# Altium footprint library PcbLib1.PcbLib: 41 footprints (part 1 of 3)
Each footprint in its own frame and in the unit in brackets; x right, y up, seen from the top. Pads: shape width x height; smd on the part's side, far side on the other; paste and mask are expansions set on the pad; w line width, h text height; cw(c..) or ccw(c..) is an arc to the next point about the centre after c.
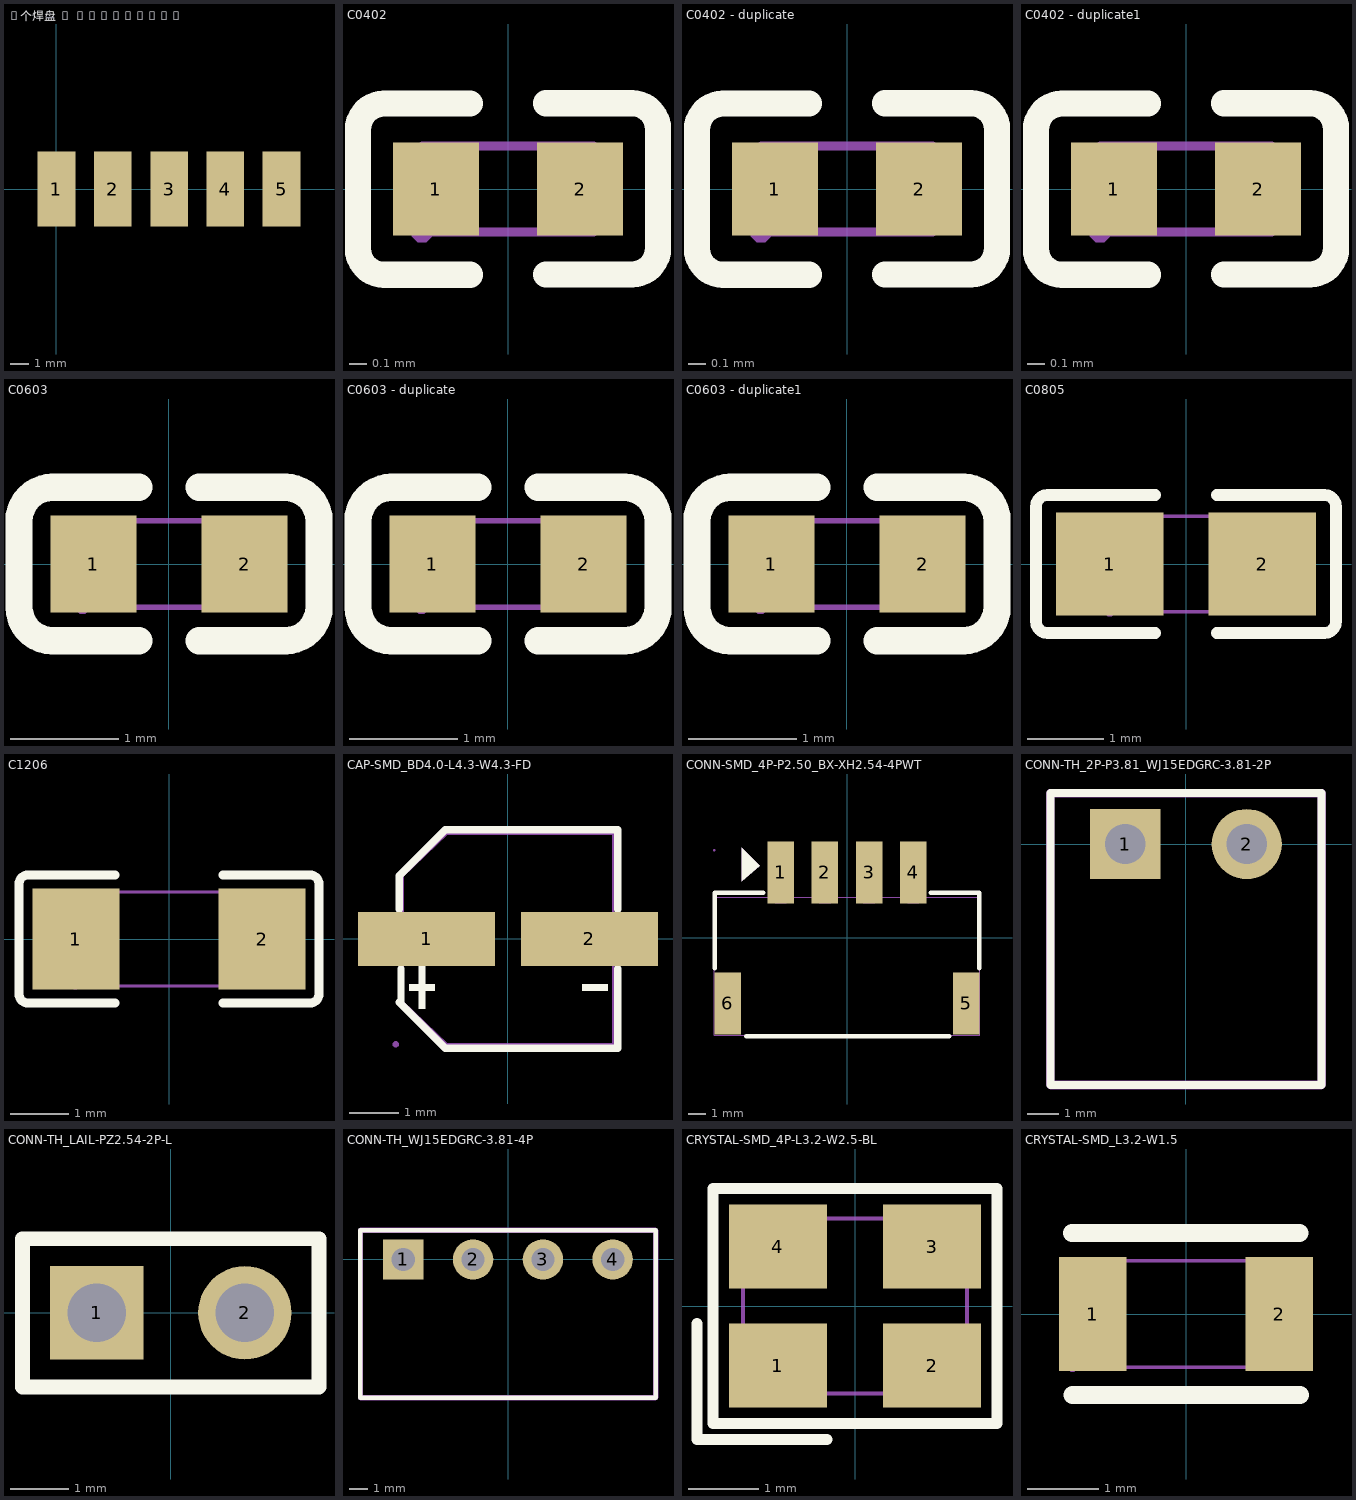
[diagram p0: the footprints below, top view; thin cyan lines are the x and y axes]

## 5个焊盘 - duplicate [mm]
pads (5):
  rect 2x4 smd: 1(0,0) 2(3,0) 3(6.001,0) 4(9,0) 5(12,0)

## C0402 [mm]
pads (2):
  rect 0.5x0.54 smd: 1(-0.42,0) 2(0.42,0)
Top Overlay:
  lines w0.152: -0.221,-0.5 -0.721,-0.5 cw(c-0.721,-0.347) -0.874,-0.347 -0.874,0.345 cw(c-0.721,0.345) -0.721,0.498 -0.221,0.498 ; 0.221,-0.498 0.721,-0.498 ccw(c0.721,-0.345) 0.874,-0.345 0.874,0.347 ccw(c0.721,0.347) 0.721,0.5 0.221,0.5
Mechanical 6:
  lines w0.051: -0.5,-0.25 0.5,-0.25 0.5,0.25 -0.5,0.25 -0.5,-0.25
Mechanical 8:
  region: -0.44,-0.25 -0.44,-0.275 -0.475,-0.31 -0.525,-0.31 -0.56,-0.275 -0.56,-0.25 -0.56,-0.225 -0.525,-0.19 -0.475,-0.19 -0.44,-0.225 -0.44,-0.25
Mechanical 9:
  region: 0.5,-0.25 0.5,0.25 0.25,0.25 0.25,-0.25
  region: -0.5,-0.25 -0.5,0.25 -0.25,0.25 -0.25,-0.25

## C0402 - duplicate [mm]
pads (2):
  rect 0.5x0.54 smd: 1(-0.42,0) 2(0.42,0)
Top Overlay:
  lines w0.152: -0.221,-0.5 -0.721,-0.5 cw(c-0.721,-0.347) -0.874,-0.347 -0.874,0.345 cw(c-0.721,0.345) -0.721,0.498 -0.221,0.498 ; 0.221,-0.498 0.721,-0.498 ccw(c0.721,-0.345) 0.874,-0.345 0.874,0.347 ccw(c0.721,0.347) 0.721,0.5 0.221,0.5
Mechanical 6:
  lines w0.051: -0.5,-0.25 0.5,-0.25 0.5,0.25 -0.5,0.25 -0.5,-0.25
Mechanical 8:
  region: -0.44,-0.25 -0.44,-0.275 -0.475,-0.31 -0.525,-0.31 -0.56,-0.275 -0.56,-0.25 -0.56,-0.225 -0.525,-0.19 -0.475,-0.19 -0.44,-0.225 -0.44,-0.25
Mechanical 9:
  region: 0.5,-0.25 0.5,0.25 0.25,0.25 0.25,-0.25
  region: -0.5,-0.25 -0.5,0.25 -0.25,0.25 -0.25,-0.25

## C0402 - duplicate1 [mm]
pads (2):
  rect 0.5x0.54 smd: 1(-0.42,0) 2(0.42,0)
Top Overlay:
  lines w0.152: -0.221,-0.5 -0.721,-0.5 cw(c-0.721,-0.347) -0.874,-0.347 -0.874,0.345 cw(c-0.721,0.345) -0.721,0.498 -0.221,0.498 ; 0.221,-0.498 0.721,-0.498 ccw(c0.721,-0.345) 0.874,-0.345 0.874,0.347 ccw(c0.721,0.347) 0.721,0.5 0.221,0.5
Mechanical 6:
  lines w0.051: -0.5,-0.25 0.5,-0.25 0.5,0.25 -0.5,0.25 -0.5,-0.25
Mechanical 8:
  region: -0.44,-0.25 -0.44,-0.275 -0.475,-0.31 -0.525,-0.31 -0.56,-0.275 -0.56,-0.25 -0.56,-0.225 -0.525,-0.19 -0.475,-0.19 -0.44,-0.225 -0.44,-0.25
Mechanical 9:
  region: 0.5,-0.25 0.5,0.25 0.25,0.25 0.25,-0.25
  region: -0.5,-0.25 -0.5,0.25 -0.25,0.25 -0.25,-0.25

## C0603 [mm]
pads (2):
  rect 0.8x0.9 smd: 1(-0.7,0) 2(0.7,0)
Top Overlay:
  lines w0.254: -1.08,-0.71 -0.28,-0.71 ; -1.08,0.71 -0.28,0.71 ; -1.08,-0.71 cw(c-1.08,-0.4) -1.39,-0.4 -1.39,0.4 cw(c-1.08,0.4) -1.08,0.71 ; 0.28,-0.71 1.08,-0.71 ccw(c1.08,-0.4) 1.39,-0.4 1.39,0.4 ccw(c1.08,0.4) 1.08,0.71 0.28,0.71
Mechanical 6:
  lines w0.051: -0.8,-0.4 -0.8,0.4 0.8,0.4 0.8,-0.4 -0.8,-0.4
Mechanical 8:
  region: -0.74,-0.4 -0.74,-0.425 -0.775,-0.46 -0.825,-0.46 -0.86,-0.425 -0.86,-0.4 -0.86,-0.375 -0.825,-0.34 -0.775,-0.34 -0.74,-0.375 -0.74,-0.4
Mechanical 9:
  region: -0.8,-0.4 -0.8,0.4 -0.5,0.4 -0.5,-0.4
  region: 0.8,-0.4 0.8,0.4 0.5,0.4 0.5,-0.4

## C0603 - duplicate [mm]
pads (2):
  rect 0.8x0.9 smd: 1(-0.7,0) 2(0.7,0)
Top Overlay:
  lines w0.254: -1.08,-0.71 -0.28,-0.71 ; -1.08,0.71 -0.28,0.71 ; -1.08,-0.71 cw(c-1.08,-0.4) -1.39,-0.4 -1.39,0.4 cw(c-1.08,0.4) -1.08,0.71 ; 0.28,-0.71 1.08,-0.71 ccw(c1.08,-0.4) 1.39,-0.4 1.39,0.4 ccw(c1.08,0.4) 1.08,0.71 0.28,0.71
Mechanical 6:
  lines w0.051: -0.8,-0.4 0.8,-0.4 0.8,0.4 -0.8,0.4 -0.8,-0.4
Mechanical 8:
  region: -0.74,-0.4 -0.74,-0.425 -0.775,-0.46 -0.825,-0.46 -0.86,-0.425 -0.86,-0.4 -0.86,-0.375 -0.825,-0.34 -0.775,-0.34 -0.74,-0.375 -0.74,-0.4
Mechanical 9:
  region: 0.8,-0.4 0.8,0.4 0.5,0.4 0.5,-0.4
  region: -0.8,-0.4 -0.8,0.4 -0.5,0.4 -0.5,-0.4

## C0603 - duplicate1 [mm]
pads (2):
  rect 0.8x0.9 smd: 1(-0.7,0) 2(0.7,0)
Top Overlay:
  lines w0.254: -1.08,-0.71 -0.28,-0.71 ; -1.08,0.71 -0.28,0.71 ; -1.08,-0.71 cw(c-1.08,-0.4) -1.39,-0.4 -1.39,0.4 cw(c-1.08,0.4) -1.08,0.71 ; 0.28,-0.71 1.08,-0.71 ccw(c1.08,-0.4) 1.39,-0.4 1.39,0.4 ccw(c1.08,0.4) 1.08,0.71 0.28,0.71
Mechanical 6:
  lines w0.051: -0.8,-0.4 -0.8,0.4 0.8,0.4 0.8,-0.4 -0.8,-0.4
Mechanical 8:
  region: -0.74,-0.4 -0.74,-0.425 -0.775,-0.46 -0.825,-0.46 -0.86,-0.425 -0.86,-0.4 -0.86,-0.375 -0.825,-0.34 -0.775,-0.34 -0.74,-0.375 -0.74,-0.4
Mechanical 9:
  region: -0.8,-0.4 -0.8,0.4 -0.5,0.4 -0.5,-0.4
  region: 0.8,-0.4 0.8,0.4 0.5,0.4 0.5,-0.4

## C0805 [mm]
pads (2):
  rect 1.41x1.35 smd paste-100 mask+0.051: 1(-1,0) 2(1,0)
Top Overlay:
  lines w0.152: -0.401,-0.904 -1.811,-0.904 cw(c-1.811,-0.751) -1.964,-0.751 -1.964,0.751 cw(c-1.811,0.751) -1.811,0.904 -0.401,0.904 ; 0.401,-0.904 1.811,-0.904 ccw(c1.811,-0.751) 1.964,-0.751 1.964,0.751 ccw(c1.811,0.751) 1.811,0.904 0.401,0.904
Top Paste:
  region: -1.705,-0.64 -1.705,0.64 -1.655,0.69 -0.505,0.69 -0.455,0.64 -0.45,0.23 -0.9,0.23 -0.9,-0.22 -0.46,-0.22 -0.455,-0.64 -0.505,-0.69 -1.655,-0.69
  region: 1.705,0.64 1.705,-0.64 1.655,-0.69 0.505,-0.69 0.455,-0.64 0.45,-0.23 0.9,-0.23 0.9,0.22 0.46,0.22 0.455,0.64 0.505,0.69 1.655,0.69
Mechanical 6:
  lines w0.051: -1,-0.625 -1,0.625 1,0.625 1,-0.625 -1,-0.625
Mechanical 8:
  region: -0.94,-0.625 -0.94,-0.65 -0.975,-0.685 -1.025,-0.685 -1.06,-0.65 -1.06,-0.625 -1.06,-0.6 -1.025,-0.565 -0.975,-0.565 -0.94,-0.6 -0.94,-0.625
Mechanical 9:
  region: -1,-0.625 -1,0.625 -0.5,0.625 -0.5,-0.625
  region: 1,0.625 1,-0.625 0.5,-0.625 0.5,0.625

## C1206 [mm]
pads (2):
  rect 1.485x1.728 smd paste-100 mask+0.051: 1(-1.593,0) 2(1.593,0)
Top Overlay:
  lines w0.152: -0.926,-1.093 -2.411,-1.093 cw(c-2.411,-0.94) -2.564,-0.94 -2.564,0.94 cw(c-2.411,0.94) -2.411,1.093 -0.926,1.093 ; 0.926,-1.093 2.411,-1.093 ccw(c2.411,-0.94) 2.564,-0.94 2.564,0.94 ccw(c2.411,0.94) 2.411,1.093 0.926,1.093
Top Paste:
  region: -0.85,-0.764 -0.85,-0.394 -0.95,-0.294 -1.255,-0.294 -1.355,-0.194 -1.355,0.194 -1.255,0.294 -0.95,0.294 -0.85,0.394 -0.85,0.764 -0.95,0.864 -2.235,0.864 -2.335,0.764 -2.335,-0.764 -2.235,-0.864 -0.95,-0.864
  region: 0.85,-0.764 0.85,-0.394 0.95,-0.294 1.255,-0.294 1.355,-0.194 1.355,0.194 1.255,0.294 0.95,0.294 0.85,0.394 0.85,0.764 0.95,0.864 2.235,0.864 2.335,0.764 2.335,-0.764 2.235,-0.864 0.95,-0.864
Mechanical 6:
  lines w0.051: -1.6,-0.8 1.6,-0.8 1.6,0.8 -1.6,0.8 -1.6,-0.8
Mechanical 8:
  region: -1.54,-0.8 -1.54,-0.825 -1.575,-0.86 -1.625,-0.86 -1.66,-0.825 -1.66,-0.8 -1.66,-0.775 -1.625,-0.74 -1.575,-0.74 -1.54,-0.775 -1.54,-0.8
Mechanical 9:
  region: 1.6,-0.8 1.6,0.8 1.1,0.8 1.1,-0.8
  region: -1.6,-0.8 -1.6,0.8 -1.1,0.8 -1.1,-0.8

## CAP-SMD_BD4.0-L4.3-W4.3-FD [mm]
pads (2):
  rect 2.8x1.1 smd: 1(-1.661,0) 2(1.661,0)
Top Overlay:
  region: -1.818,-0.559 -1.818,-1.419 -1.689,-1.419 -1.689,-0.559
  region: -2.011,-0.925 -2.011,-1.054 -1.495,-1.054 -1.495,-0.925
  region: 2.031,-0.925 2.031,-1.054 1.515,-1.054 1.515,-0.925
  lines w0.152: -2.217,-1.29 -1.28,-2.226 2.236,-2.226 2.236,-0.607 ; -2.217,0.607 -2.217,1.29 -1.28,2.226 2.236,2.226 2.236,0.607 ; -2.183,-1.29 -2.183,-0.607
Mechanical 2:
  region: -1.818,0.43 -1.818,-0.43 -1.689,-0.43 -1.689,0.43
  region: -2.011,0.064 -2.011,-0.065 -1.495,-0.065 -1.495,0.064
  region: 2.031,0.064 2.031,-0.065 1.515,-0.065 1.515,0.064
Mechanical 6:
  lines w0.051: -2.15,-1.281 -2.15,1.281 -1.248,2.15 2.15,2.15 2.15,-2.15 -1.248,-2.15 -2.15,-1.281
Mechanical 8:
  region: -2.23,-2.15 -2.23,-2.175 -2.266,-2.21 -2.315,-2.21 -2.35,-2.175 -2.35,-2.15 -2.35,-2.125 -2.315,-2.09 -2.266,-2.09 -2.23,-2.125 -2.23,-2.15
Mechanical 9:
  region: -2.29,0.325 -2.29,-0.325 -0.49,-0.325 -0.49,0.325
  region: 2.31,0.325 2.31,-0.325 0.51,-0.325 0.51,0.325

## CONN-SMD_4P-P2.50_BX-XH2.54-4PWT [mm]
pads (6):
  rect 1.5x3.5 smd paste+0 mask+0.05: 1(-3.75,3.7) 2(-1.25,3.7) 3(1.25,3.7) 4(3.75,3.7) 5(6.73,-3.7) 6(-6.73,-3.7)
Top Overlay:
  region: -4.946,4.081 -5.962,5.097 -5.962,3.192
  lines w0.254: -7.486,-1.719 -7.486,2.557 -4.731,2.557 ; -5.708,-5.571 5.783,-5.571 ; 4.73,2.558 6.389,2.558 7.486,2.558 7.486,-1.719
Mechanical 2:
  region: -4.946,4.081 -5.962,5.097 -5.962,3.192
Mechanical 6:
  lines w0.051: -7.5,-5.502 7.5,-5.502 7.5,2.298 -7.5,2.298 -7.5,-5.502
Mechanical 8:
  region: -7.44,4.95 -7.44,4.925 -7.475,4.89 -7.525,4.89 -7.56,4.925 -7.56,4.95 -7.56,4.975 -7.525,5.01 -7.475,5.01 -7.44,4.975 -7.44,4.95
Mechanical 9:
  region: 6.53,-2.45 6.93,-2.45 6.93,-4.95 6.53,-4.95
  region: -6.93,-2.45 -6.53,-2.45 -6.53,-4.95 -6.93,-4.95
  region: 3.43,4.95 4.07,4.95 4.07,1.95 3.43,1.95
  region: 0.93,4.95 1.57,4.95 1.57,1.95 0.93,1.95
  region: -1.57,4.95 -0.93,4.95 -0.93,1.95 -1.57,1.95
  region: -4.07,4.95 -3.43,4.95 -3.43,1.95 -4.07,1.95

## CONN-TH_2P-P3.81_WJ15EDGRC-3.81-2P [mm]
pads (2):
  rect 2.2x2.2 hole 1.26: 1(-1.905,0)
  round 2.2 hole 1.26: 2(1.905,0)
Top Overlay:
  lines w0.254: -4.25,-7.55 -4.25,1.6 4.25,1.6 4.25,-7.55 -4.25,-7.55
Mechanical 2:
  region: -4.123,1.6 -4.123,-7.423 4.123,-7.423 4.123,1.6 4.133,1.649 4.16,1.69 4.201,1.717 4.25,1.727 4.299,1.717 4.34,1.69 4.367,1.649 4.377,1.6 4.377,-7.55 4.367,-7.599 4.34,-7.64 4.299,-7.667 4.25,-7.677 -4.25,-7.677 -4.299,-7.667 -4.34,-7.64 -4.367,-7.599 -4.377,-7.55 -4.377,1.6 -4.367,1.649 -4.34,1.69 -4.299,1.717 -4.25,1.727 -4.201,1.717 -4.16,1.69 -4.133,1.649
  region: 4.25,1.473 -4.25,1.473 -4.299,1.483 -4.34,1.51 -4.367,1.551 -4.377,1.6 -4.367,1.649 -4.34,1.69 -4.299,1.717 -4.25,1.727 4.25,1.727 4.299,1.717 4.34,1.69 4.367,1.649 4.377,1.6 4.367,1.551 4.34,1.51 4.299,1.483
Mechanical 6:
  lines w0.051: -4.25,-7.55 -4.25,1.6 4.25,1.6 4.25,-7.55 -4.25,-7.55
Mechanical 8:
  region: -4.19,-7.55 -4.19,-7.575 -4.225,-7.61 -4.275,-7.61 -4.31,-7.575 -4.31,-7.55 -4.31,-7.525 -4.275,-7.49 -4.225,-7.49 -4.19,-7.525 -4.19,-7.55
Mechanical 9:
  region: 1.505,0.4 2.305,0.4 2.305,-0.4 1.505,-0.4
  region: -2.305,0.4 -1.505,0.4 -1.505,-0.4 -2.305,-0.4

## CONN-TH_LAIL-PZ2.54-2P-L [mm]
pads (2):
  rect 1.6x1.6 hole 1 paste-2539.97 mask+0.05: 1(-1.27,0)
  round 1.6 hole 1 paste-2539.97 mask+0.05: 2(1.27,0)
Top Overlay:
  lines w0.254: -2.54,-1.27 -2.54,1.27 2.54,1.27 2.54,-1.27 -2.54,-1.27
Mechanical 6:
  lines w0.051: -2.54,-1.25 -2.54,1.25 2.54,1.25 2.54,-1.25 -2.54,-1.25
Mechanical 8:
  region: -2.48,-1.25 -2.48,-1.275 -2.515,-1.31 -2.565,-1.31 -2.6,-1.275 -2.6,-1.25 -2.6,-1.225 -2.565,-1.19 -2.515,-1.19 -2.48,-1.225 -2.48,-1.25
Mechanical 9:
  region: -1.59,0.32 -0.95,0.32 -0.95,-0.32 -1.59,-0.32
  region: 0.95,0.32 1.59,0.32 1.59,-0.32 0.95,-0.32

## CONN-TH_WJ15EDGRC-3.81-4P [mm]
pads (4):
  rect 2.2x2.2 hole 1.26: 1(-5.715,0)
  round 2.2 hole 1.26: 2(-1.905,0) 3(1.905,0) 4(5.715,0)
Top Overlay:
  lines w0.254: -8.06,-7.55 -8.06,1.6 8.06,1.6 8.06,-7.55 -8.06,-7.55
Mechanical 2:
  region: -7.933,1.6 -7.933,-7.423 7.933,-7.423 7.933,1.6 7.943,1.649 7.97,1.69 8.011,1.717 8.06,1.727 8.109,1.717 8.15,1.69 8.177,1.649 8.187,1.6 8.187,-7.55 8.177,-7.599 8.15,-7.64 8.109,-7.667 8.06,-7.677 -8.06,-7.677 -8.109,-7.667 -8.15,-7.64 -8.177,-7.599 -8.187,-7.55 -8.187,1.6 -8.177,1.649 -8.15,1.69 -8.109,1.717 -8.06,1.727 -8.011,1.717 -7.97,1.69 -7.943,1.649
  region: 8.06,1.473 -8.06,1.473 -8.109,1.483 -8.15,1.51 -8.177,1.551 -8.187,1.6 -8.177,1.649 -8.15,1.69 -8.109,1.717 -8.06,1.727 8.06,1.727 8.109,1.717 8.15,1.69 8.177,1.649 8.187,1.6 8.177,1.551 8.15,1.51 8.109,1.483
Mechanical 6:
  lines w0.051: -8.06,-7.55 -8.06,1.6 8.06,1.6 8.06,-7.55 -8.06,-7.55
Mechanical 8:
  region: -8,-7.55 -8,-7.575 -8.035,-7.61 -8.085,-7.61 -8.12,-7.575 -8.12,-7.55 -8.12,-7.525 -8.085,-7.49 -8.035,-7.49 -8,-7.525 -8,-7.55
Mechanical 9:
  region: -6.115,0.4 -5.315,0.4 -5.315,-0.4 -6.115,-0.4
  region: -2.305,0.4 -1.505,0.4 -1.505,-0.4 -2.305,-0.4
  region: 1.505,0.4 2.305,0.4 2.305,-0.4 1.505,-0.4
  region: 5.315,0.4 6.115,0.4 6.115,-0.4 5.315,-0.4

## CRYSTAL-SMD_4P-L3.2-W2.5-BL [mm]
pads (4):
  rect 1.4x1.2 smd: 1(-1.1,-0.85) 2(1.1,-0.85) 3(1.1,0.85) 4(-1.1,0.85)
Top Overlay:
  lines w0.152: -2.257,-0.25 -2.257,-1.907 -0.4,-1.907 ; -2.029,-1.678 -2.029,1.679 2.029,1.679 2.029,-1.678 -2.029,-1.678
Mechanical 2:
  circle w0.254: c-1.27,-0.889 r0.127
Mechanical 6:
  lines w0.051: -1.6,-1.25 -1.6,1.25 1.6,1.25 1.6,-1.25 -1.6,-1.25
Mechanical 8:
  region: -1.54,-1.25 -1.54,-1.275 -1.575,-1.31 -1.625,-1.31 -1.66,-1.275 -1.66,-1.25 -1.66,-1.225 -1.625,-1.19 -1.575,-1.19 -1.54,-1.225 -1.54,-1.25
Mechanical 9:
  region: -1.5,1.15 -0.6,1.15 -0.6,0.35 -1.5,0.35
  region: 0.6,1.15 1.5,1.15 1.5,0.35 0.6,0.35
  region: 0.6,-0.35 1.5,-0.35 1.5,-1.15 0.6,-1.15
  region: -1.5,-0.35 -0.6,-0.35 -0.6,-1.15 -1.5,-1.15

## CRYSTAL-SMD_L3.2-W1.5 [mm]
pads (2):
  rect 0.95x1.6 smd: 1(-1.308,0) 2(1.308,0)
Top Overlay:
  lines w0.254: -1.603,1.14 1.597,1.14 ; -1.597,-1.14 1.603,-1.14
Mechanical 6:
  lines w0.051: -1.597,-0.75 1.603,-0.75 1.603,0.75 -1.597,0.75 -1.597,-0.75
Mechanical 8:
  region: -1.537,-0.75 -1.537,-0.775 -1.573,-0.81 -1.622,-0.81 -1.657,-0.775 -1.657,-0.75 -1.657,-0.725 -1.622,-0.69 -1.573,-0.69 -1.537,-0.725 -1.537,-0.75
Mechanical 9:
  region: -1.598,-0.65 -1.598,0.65 -0.847,0.65 -0.847,-0.65
  region: 0.853,-0.65 0.853,0.65 1.603,0.65 1.603,-0.65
